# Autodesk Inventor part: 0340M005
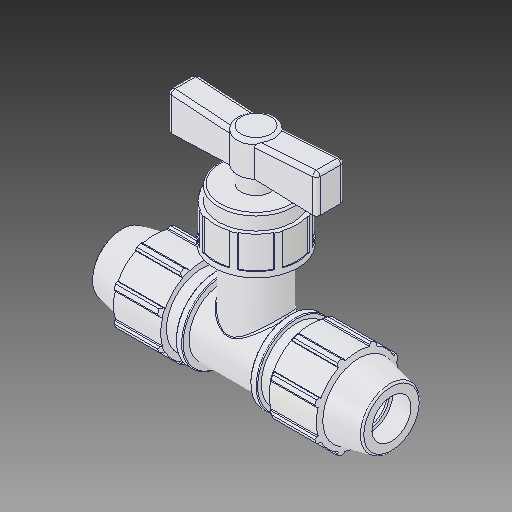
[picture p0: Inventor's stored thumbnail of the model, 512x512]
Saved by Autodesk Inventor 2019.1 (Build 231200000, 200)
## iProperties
Created: 2017-02
Part Number: 0340M005
Material: PVC-Piping
Description: PLASSON COMPRESSION STOPTAP 1/2'' - 1/2''
Document SubType Name: Modeling
Designer: KIM
Mass: 92.6774 g
Surface Area: 199.44 cm^2
Volume: 66.1981 cm^3
Density: 1.4 g/cm^3
Appearance: PTFE
Author: KIM
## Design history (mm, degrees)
derived "0340M0.ipt"
feature "Solid1::0340M0.ipt"
tag "TaggingFeature1"
body "Solid1"
other parameters: "d_" = 21.2, "E_" = 48.006, "H_" = 147.066, "l_" = 57.912, "A_" = 101.092, "d67" = 92, "d78" = 45.4914, "d1" = 147.066, "d2" = 21.2, "d4" = 12.2555, "d5" = 17.64792, "d7" = 48.006, "d8" = 36.0045, "d9" = 36.7665, "d11" = 3.67665, "d12" = 38.4048, "d13" = 120 deg, "d14" = 31.8, "d15" = 12 deg, "d16" = 43.2054, "d18" = 1.06, "d19" = 35 deg, "d20" = 17.5 deg, "d21" = 44.64558, "d23" = 0, "d25" = 360 deg, "d27" = 0.96012, "d33" = 0.424, "d42" = 26.47188, "d43" = 1.44018, "d46" = 0.636, "d49" = 57.912, "d50" = 16.96, "d51" = 101.092, "d53" = 20.2184, "d54" = 20.2184, "d57" = 18.19656, "d60" = 45.4914, "d61" = 30.3276, "d62" = 20.2184, "d63" = 65.7098, "d64" = 16.17472, "d65" = 40.4368, "d66" = 8.08736, "d69" = 13.64742, "d70" = 6.82371, "d71" = 44.58157, "d72" = 41.4, "d74" = 0, "d75" = 17.18564, "d76" = 92, "d77" = 92, "d80" = 360 deg, "d82" = 0.40437, "d85" = 40.4368, "d86" = 6 deg, "d87" = 94 deg, "d88" = 15.1638, "d89" = 0, "d90" = 2, "d91" = 2, "d92" = 1.01092, "d93" = 1.01092
